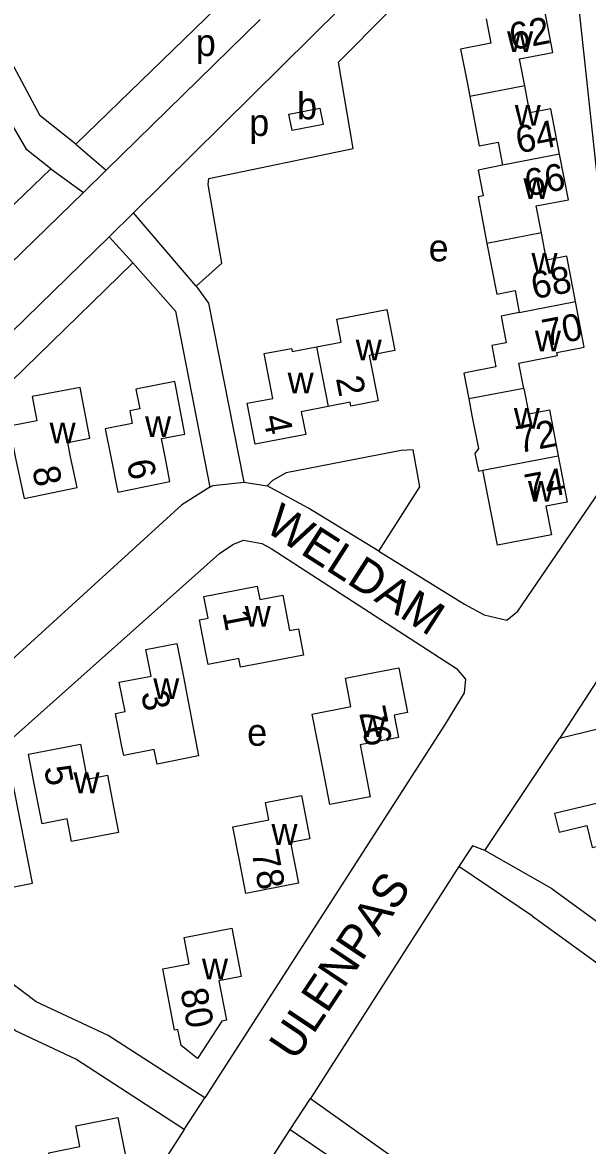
# Model space of a CAD drawing. Extents: x 157646 to 159241, y 379213 to 381217.
# Drawn here: x 158329.1 to 158413, y 380397.8 to 380564.5 of the extents above; entities that cross this region are included whole.
import ezdxf

# ---------------------------------------------------------------- set-up
doc = ezdxf.new("R2010")
doc.units = 0
for name, color, linetype in [('BLT_Basislijn', 7, 'Continuous'), ('BLT_Bebouwing', 7, 'Continuous'), ('BLT_Centroide', 7, 'Continuous'), ('BLT_Huisnummer', 7, 'Continuous'), ('BLT_Onderverdeling_panden', 7, 'Continuous'), ('BLT_Straatnaam', 7, 'Continuous')]:
    doc.layers.add(name, color=color, linetype=linetype)

msp = doc.modelspace()

# ---------------------------------------------------------------- linework, layer by layer
at = {"layer": 'BLT_Basislijn'}
for p, q in [((158337.01, 380546.43), (158362.89, 380571.52)), ((158341.49, 380542.56), (158364.39, 380564.93)), ((158337.01, 380546.43), (158341.49, 380542.56)), ((158333.3, 380542.79), (158270.39, 380482.44)), ((158333.3, 380542.79), (158338.15, 380539.27)), ((158338.15, 380539.27), (158341.49, 380542.56)), ((158338.15, 380539.27), (158273.9, 380476.9)), ((158341.93, 380532.68), (158345.58, 380536.24)), ((158354.88, 380525.33), (158345.58, 380536.24)), ((158281.54, 380473.72), (158341.93, 380532.68)), ((158345.48, 380528.82), (158341.93, 380532.68)), ((158345.48, 380528.82), (158284.27, 380469.15)), ((158361.93, 380496.25), (158365.41, 380495.7)), ((158459.75, 380470.6), (158408.83, 380458.22)), ((158415.6, 380468.65), (158408.83, 380458.22)), ((158397.71, 380441.59), (158408.83, 380458.22)), ((158407.74, 380435.87), (158397.71, 380441.59)), ((158393.89, 380439.2), (158371.84, 380404.74)), ((158404.8, 380431.83), (158393.89, 380439.2)), ((158407.74, 380435.87), (158416.7, 380429.36)), ((158353.1, 380400.13), (158356.18, 380404.83)), ((158368.81, 380400.14), (158371.84, 380404.74)), ((158362.2, 380389.9), (158368.81, 380400.14))]:
    msp.add_line(p, q, dxfattribs=at)
for points in [[(158345.58, 380536.24), (158402.72, 380592.79), (158408.77, 380593.57)], [(158354.88, 380525.33), (158358.68, 380528.77), (158356.65, 380540.46), (158356.75, 380541.31), (158378.2, 380545.77), (158375.99, 380558.59), (158398.1, 380580.88), (158409.95, 380583.17)], [(158382, 380486.03), (158394.7, 380478.15), (158397.65, 380476.58), (158401, 380475.76), (158402.65, 380477.1), (158414.74, 380494.85), (158416.53, 380498.98), (158417.47, 380503.76), (158417.68, 380511.48), (158409.95, 380583.17)], [(158337.01, 380546.43), (158331.69, 380550.62), (158324.66, 380563.71)], [(158333.3, 380542.79), (158329.75, 380545.57), (158324.69, 380554.22), (158321.31, 380560.74)], [(158345.48, 380528.82), (158351.8, 380521.65), (158356.9, 380495.51)], [(158354.88, 380525.33), (158356.7, 380522.85), (158361.93, 380496.25)], [(158382, 380486.03), (158388.08, 380495.55), (158387.11, 380501.03), (158385.3, 380500.94), (158368.21, 380497.64), (158366.21, 380496.5), (158365.41, 380495.7)], [(158356.9, 380495.51), (158357.38, 380495.78), (158361.93, 380496.25)], [(158356.9, 380495.51), (158352.76, 380492.88), (158317.31, 380460.61), (158311.07, 380454.22), (158301.07, 380439.61)], [(158382, 380486.03), (158371.46, 380492.45), (158365.41, 380495.7)], [(158309.01, 380435.78), (158314.99, 380445.5), (158320.3, 380451.83), (158358.31, 380485.67), (158360.33, 380487), (158361.92, 380487.62), (158364.63, 380487.17), (158366, 380486.42), (158393.52, 380468.6), (158394.86, 380467.01), (158394.65, 380464.96), (158391.74, 380460.19), (158356.18, 380404.83)], [(158397.71, 380441.59), (158395.91, 380442.27), (158395.38, 380441.52), (158393.89, 380439.2)], [(158356.18, 380404.83), (158341.81, 380414.09), (158331.1, 380419.09), (158309.01, 380435.78)], [(158353.1, 380400.13), (158337.01, 380410.59), (158328.02, 380414.79), (158305.95, 380431.25)], [(158404.8, 380431.83), (158418.11, 380422.16), (158433.89, 380414.67), (158447.97, 380405.16)], [(158371.84, 380404.74), (158408.18, 380378.92), (158409.65, 380377.6), (158411.02, 380375.86), (158413.89, 380370.53), (158415.7, 380360.95), (158417.2, 380357.34), (158418.61, 380354.92), (158421.49, 380351.01), (158424.52, 380348.6), (158429.22, 380345.84), (158436.86, 380344.43), (158443.38, 380345.1), (158477.93, 380359), (158481.57, 380360.73), (158481.57, 380361.05), (158447.97, 380405.16)], [(158353.1, 380400.13), (158320.33, 380349.18), (158315.53, 380342.75), (158309.04, 380337.25), (158301.78, 380333.59), (158255.93, 380325.04)], [(158368.81, 380400.14), (158402.75, 380377.05), (158407.65, 380371.93), (158410.45, 380365.82), (158411.25, 380359.98), (158412.3, 380355.98), (158415.5, 380350.01), (158417.71, 380347.9)]]:
    msp.add_lwpolyline(points, dxfattribs=at)
at = {"layer": 'BLT_Bebouwing'}
for p, q in [((158402.85, 380521.44), (158411.19, 380523.05)), ((158352.97, 380467.37), (158355.24, 380455.61))]:
    msp.add_line(p, q, dxfattribs=at)
for points in [[(158403.65, 380555.07), (158402.88, 380559.08), (158407.85, 380560.04), (158406.56, 380566.72)], [(158397.91, 380565.06), (158398.61, 380561.41), (158394.14, 380560.55), (158395.09, 380555.64), (158395.5, 380553.5)], [(158408.83, 380544.93), (158407.53, 380551.66), (158404.42, 380551.06), (158403.65, 380555.07)], [(158395.5, 380553.5), (158396.91, 380546.18), (158399.7, 380546.72), (158400.36, 380543.29)], [(158369.12, 380548.47), (158368.65, 380550.9), (158373.24, 380551.78), (158373.71, 380549.35), (158369.12, 380548.47)], [(158406.14, 380533.25), (158405.36, 380537.27), (158410.13, 380538.19), (158408.83, 380544.93)], [(158400.36, 380543.29), (158396.72, 380542.59), (158397.46, 380538.74), (158396.72, 380538.6), (158398.05, 380531.69)], [(158411.19, 380523.05), (158409.89, 380529.8), (158406.91, 380529.23), (158406.14, 380533.25)], [(158398.05, 380531.69), (158399.5, 380524.18), (158402.22, 380524.71), (158402.85, 380521.44)], [(158403.52, 380510.18), (158402.8, 380513.94), (158408.52, 380515.04), (158408.43, 380515.51), (158412.49, 380516.29), (158411.19, 380523.05)], [(158372.75, 380516.34), (158376.41, 380517.05), (158375.75, 380520.44), (158383.2, 380521.88), (158384.37, 380515.79), (158380.58, 380515.06), (158381.88, 380508.32), (158377.85, 380507.54), (158377.74, 380508.11), (158374.46, 380507.48)], [(158402.85, 380521.44), (158400.15, 380520.92), (158400.92, 380516.94), (158398.76, 380516.52), (158399.37, 380513.35), (158394.61, 380512.43), (158395.34, 380508.61)], [(158374.46, 380507.48), (158370.48, 380506.71), (158371.13, 380503.35), (158363.63, 380501.9), (158362.46, 380507.96), (158366.23, 380508.69), (158364.95, 380515.33), (158369.01, 380516.11), (158369.1, 380515.64), (158372.75, 380516.34)], [(158350.25, 380500), (158349.72, 380502.73), (158353.2, 380503.4), (158351.7, 380511.18), (158345.93, 380510.08), (158346.5, 380507.15), (158345.02, 380506.86), (158345.38, 380504.96), (158341.38, 380504.19), (158342.18, 380500), (158343.22, 380494.77), (158350.97, 380496.36), (158350.25, 380500)], [(158336.22, 380500), (158335.8, 380502.15), (158339.09, 380502.79), (158337.64, 380510.32), (158330.53, 380508.95), (158331.22, 380505.35), (158327.13, 380504.56), (158328.01, 380499.99), (158329.31, 380493.82), (158337.18, 380495.44), (158336.22, 380500)], [(158403.52, 380510.18), (158404.25, 380506.42), (158407.32, 380507.01), (158408.64, 380500.15)], [(158395.34, 380508.61), (158395.82, 380506.14), (158396.77, 380501.23), (158396.27, 380500.5), (158396.77, 380497.88), (158397.45, 380498.01)], [(158408.64, 380500.15), (158409.95, 380493.29), (158406.79, 380492.68), (158407.61, 380488.44), (158399.59, 380486.9), (158397.45, 380498.01)], [(158365.89, 380469.63), (158361.46, 380468.78), (158361.22, 380470.05), (158356.66, 380469.16), (158356.32, 380470.92), (158355.37, 380475.83), (158356.64, 380476.08), (158356.02, 380479.3), (158363.91, 380480.83), (158364.3, 380478.81), (158367.72, 380479.47), (158368.73, 380474.24), (158370.04, 380474.49), (158370.8, 380470.58), (158365.89, 380469.63)], [(158355.24, 380455.61), (158349.06, 380454.41), (158348.65, 380456.57), (158344.11, 380455.69), (158343.85, 380457.01), (158342.9, 380461.92), (158344.31, 380462.19), (158343.46, 380466.55), (158348.18, 380467.46), (158347.42, 380471.39), (158352.02, 380472.28), (158352.97, 380467.37)], [(158380.04, 380467.73), (158384.95, 380468.68), (158386.23, 380462.05), (158384.25, 380461.67), (158384.89, 380458.37), (158379.21, 380457.28), (158380.7, 380449.55), (158374.71, 380448.39), (158373.76, 380453.3), (158372.09, 380461.79), (158377.83, 380462.95), (158377.02, 380467.14), (158380.04, 380467.73)], [(158342.65, 380447.82), (158343.35, 380444.26), (158336.38, 380442.91), (158335.72, 380446.27), (158331.98, 380445.55), (158330.93, 380450.97), (158329.98, 380455.88), (158337.68, 380457.37), (158338.69, 380452.14), (158341.71, 380452.73), (158342.65, 380447.82)], [(158420.16, 380452.92), (158416.98, 380452.16), (158417.65, 380449.34), (158408.09, 380447.07), (158408.75, 380444.29), (158412.89, 380445.27), (158413.66, 380442.02), (158416.5, 380442.7), (158417.17, 380439.86), (158422.04, 380441.01), (158422.94, 380441.23), (158422.25, 380444.11)], [(158318.49, 380440.58), (158319.58, 380440.79), (158319.84, 380439.46), (158321.24, 380438.51), (158322.94, 380438.84), (158327.08, 380436.05), (158330.55, 380436.72), (158327.61, 380451.91), (158324.09, 380451.23), (158324.39, 380449.71), (158322.95, 380449.43), (158321.54, 380447.34), (158319.6, 380446.96), (158318.58, 380445.45), (158318.64, 380445.15), (158317.64, 380444.96), (158318.49, 380440.58)], [(158370.82, 380448.22), (158371.77, 380443.31), (158368.9, 380442.76), (158370.08, 380436.71), (158362.23, 380435.19), (158361.28, 380440.1), (158360.31, 380445.09), (158365.67, 380446.12), (158365.17, 380448.7), (158370.53, 380449.74), (158370.82, 380448.22)], [(158349.9, 380424.01), (158353.84, 380424.77), (158353.09, 380428.65), (158360.18, 380430.02), (158361.57, 380422.87), (158358.22, 380422.22), (158359.35, 380416.37), (158358.7, 380416.25)], [(158358.7, 380416.25), (158355.09, 380410.68), (158352.62, 380412.6), (158352.17, 380414.98), (158351.67, 380414.89), (158349.9, 380424.01)], [(158332.98, 380396.71), (158337.6, 380397.61), (158337, 380400.71), (158343.25, 380401.93), (158344.8, 380394), (158341.69, 380393.39), (158342.3, 380390.3), (158339.17, 380389.69), (158339.62, 380387.42), (158334.98, 380386.51), (158332.98, 380396.71)]]:
    msp.add_lwpolyline(points, dxfattribs=at)
at = {"layer": 'BLT_Onderverdeling_panden'}
for p, q in [((158403.65, 380555.07), (158395.5, 380553.5)), ((158408.83, 380544.93), (158400.36, 380543.29)), ((158406.14, 380533.25), (158398.05, 380531.69)), ((158372.75, 380516.34), (158374.46, 380507.48)), ((158403.52, 380510.18), (158395.34, 380508.61)), ((158397.45, 380498.01), (158408.64, 380500.15))]:
    msp.add_line(p, q, dxfattribs=at)

# ---------------------------------------------------------------- texts
at = {"layer": 'BLT_Centroide'}
for s, p in [('p', (158354.81, 380559.52)), ('w', (158401.03, 380560.12)), ('b', (158369.85, 380550.12)), ('w', (158402.17, 380549.19)), ('p', (158362.75, 380547.65)), ('w', (158403.45, 380538.31)), ('e', (158389.39, 380529.04)), ('w', (158404.66, 380527.19)), ('w', (158405.16, 380515.66)), ('w', (158378.56, 380514.33)), ('w', (158368.45, 380509.42)), ('w', (158347.28, 380502.97)), ('w', (158402.04, 380504.19)), ('w', (158333.11, 380502.02)), ('w', (158404.14, 380493.34)), ('w', (158362.09, 380474.81)), ('w', (158348.5, 380464.06)), ('w', (158379.16, 380458.41)), ('e', (158362.44, 380457.12)), ('w', (158336.66, 380450.08)), ('w', (158366.05, 380442.41)), ('w', (158355.73, 380422.42))]:
    msp.add_text(s, height=4, dxfattribs=at).set_placement(p)
at = {"layer": 'BLT_Huisnummer'}
for s, rotation, p in [('62', 10.8928, (158401.8, 380560.36)), ('64', 10.8928, (158402.72, 380545.03)), ('66', 10.8928, (158404.08, 380538.65)), ('68', 10.8928, (158405.02, 380523.4)), ('70', 10.8928, (158406.65, 380516.38)), ('2', 280.8994, (158375.6, 380511.68)), ('4', 280.9076, (158364.79, 380505.98)), ('72', 10.8928, (158402.8, 380500.55)), ('6', 281.2362, (158344.53, 380499.28)), ('8', 281.2362, (158330.51, 380498.27)), ('74', 10.8928, (158404.08, 380493.39)), ('1', 280.9548, (158358.75, 380476.92)), ('3', 280.9548, (158346.67, 380464.96)), ('76', 281.1296, (158378.95, 380462.65)), ('5', 280.9541, (158332.25, 380453.85)), ('78', 280.9526, (158363.07, 380441.34)), ('80', 280.9545, (158352.49, 380420.78))]:
    msp.add_text(s, height=4, rotation=rotation, dxfattribs=at).set_placement(p)
at = {"layer": 'BLT_Straatnaam'}
for s, rotation, p in [('WELDAM', 327.3935, (158364.85, 380489.13)), ('ULENPAS', 56.2624, (158369.57, 380410.15))]:
    msp.add_text(s, height=5, rotation=rotation, dxfattribs=at).set_placement(p)

doc.saveas('drawing.dxf')
